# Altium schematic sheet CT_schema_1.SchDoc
size 591 x 258 mm
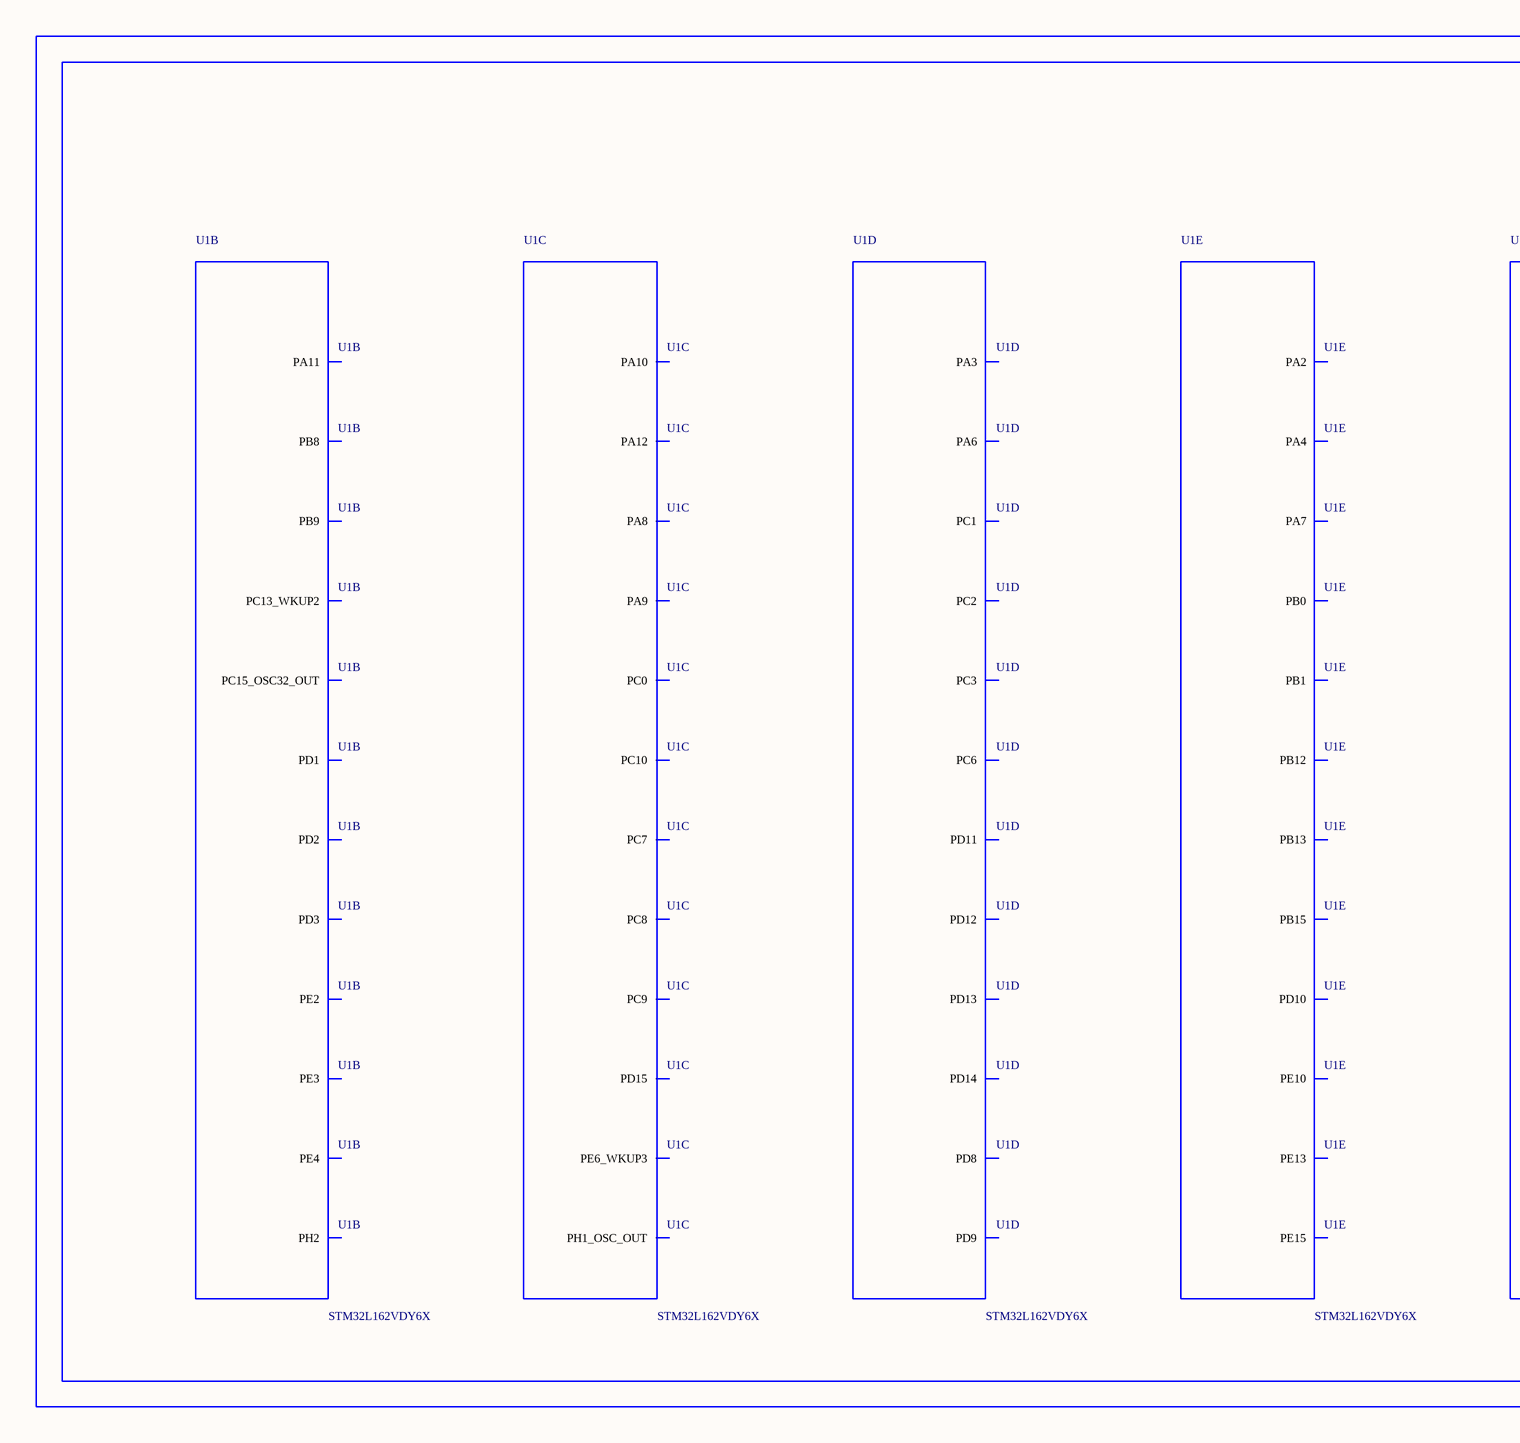
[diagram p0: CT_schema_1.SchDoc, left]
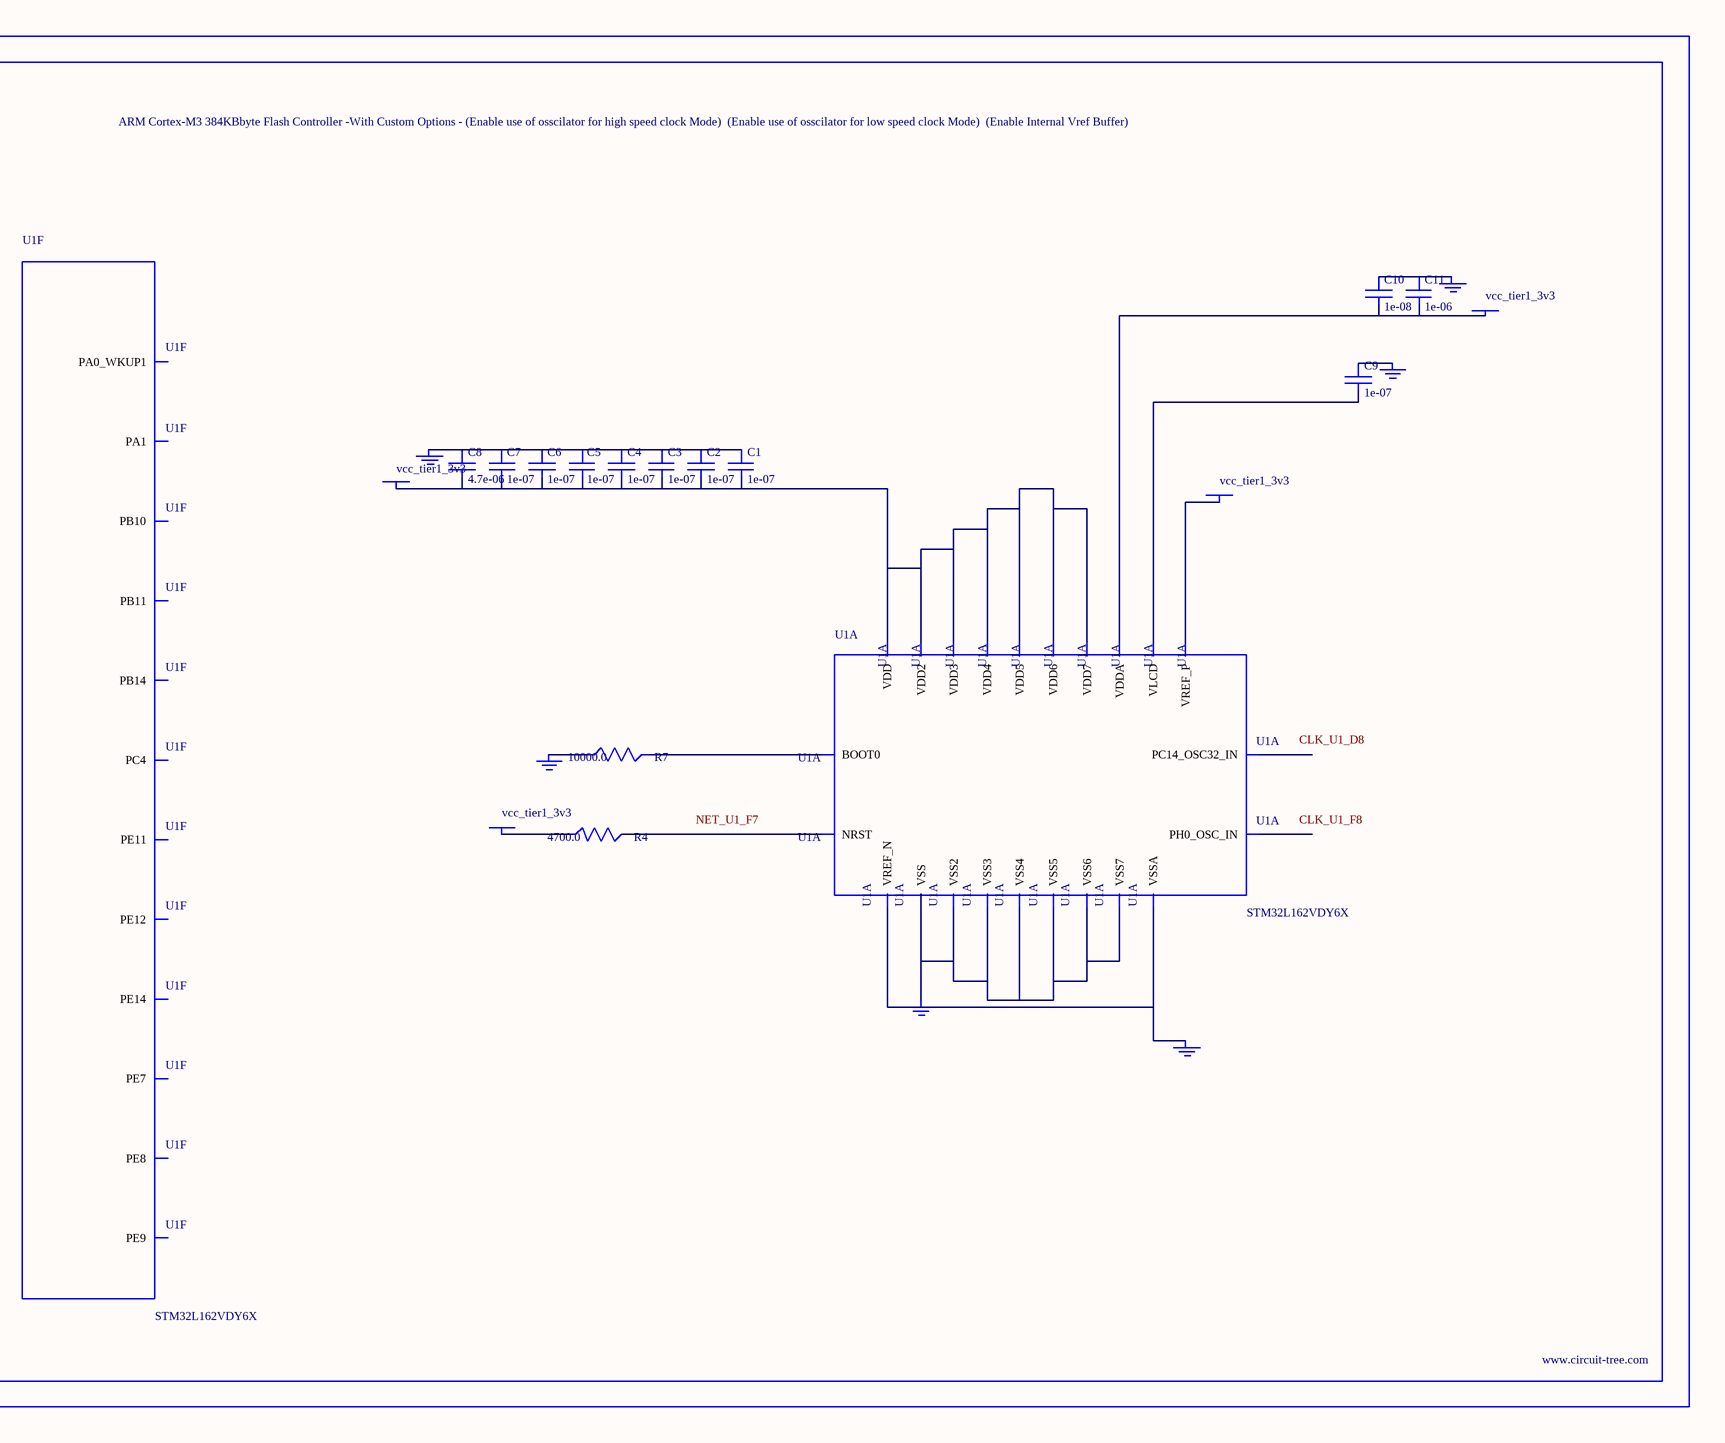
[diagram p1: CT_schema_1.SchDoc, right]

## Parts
BORDER0  (no value)
C1  1e-07  [C0603]
C2  1e-07  [C0603]
C3  1e-07  [C0603]
C4  1e-07  [C0603]
C5  1e-07  [C0603]
C6  1e-07  [C0603]
C7  1e-07  [C0603]
C8  4.7e-06  [C0603]
C9  1e-07  [C0603]
C10  1e-08  [C0603]
C11  1e-06  [C0603]
GND_INSTANCE_0_0  (no value)
GND_INSTANCE_0_1  (no value)
GND_INSTANCE_0_2  (no value)
GND_INSTANCE_0_3  (no value)
GND_INSTANCE_0_4  (no value)
GND_INSTANCE_0_5  (no value)
POWER_INSTANCE_0_0  vcc_tier1_3v3
POWER_INSTANCE_0_1  vcc_tier1_3v3
POWER_INSTANCE_0_2  vcc_tier1_3v3
POWER_INSTANCE_0_3  vcc_tier1_3v3
R4  4700.0  [R0603]
R7  10000.0  [R0603]
U1  STM32L162VDY6X  [WLCSP104]  (parts A,B,C,D,E,F of 9)

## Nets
NetC1_1: C1.1 C2.1 C3.1 C4.1 C5.1 C6.1 C7.1 C8.1 GND_INSTANCE_0_0.0(GND)
NetC1_2: C1.2 C2.2 C3.2 C4.2 C5.2 C6.2 C7.2 C8.2 POWER_INSTANCE_0_0.0(PWR) U1.A9(VDD) U1.B8(VDD2) U1.C1(VDD3) U1.E9(VDD4) U1.K3(VDD5) U1.L8(VDD6) U1.M9(VDD7)
NetC9_1: C9.1 GND_INSTANCE_0_1.0(GND)
NetC9_2: C9.2 U1.E7(VLCD)
NetC10_1: C10.1 C11.1 GND_INSTANCE_0_3.0(GND)
NetC10_2: C10.2 C11.2 POWER_INSTANCE_0_1.0(PWR) U1.G6(VDDA)
NetGND_INSTANCE_0_2_0: GND_INSTANCE_0_2.0(GND) R7.1
NetGND_INSTANCE_0_4_0: GND_INSTANCE_0_4.0(GND) U1.H8(VREF_N) U1.J9(VSSA)
NetGND_INSTANCE_0_5_0: GND_INSTANCE_0_5.0(GND) U1.A1(VSS) U1.C7(VSS2) U1.D2(VSS3) U1.E8(VSS4) U1.K8(VSS5) U1.L2(VSS6) U1.M1(VSS7)
NetPOWER_INSTANCE_0_2_0: POWER_INSTANCE_0_2.0(PWR) U1.G7(VREF_P)
NetPOWER_INSTANCE_0_3_0: POWER_INSTANCE_0_3.0(PWR) R4.1
NetR4_2: R4.2 U1.F7(NRST)
NetR7_2: R7.2 U1.A7(BOOT0)

Not connected (* = marked no-connect by the designer): U1 C3(PD2) C4(PD3) C6(PB9) C8(PE4) C9(PC13_WKUP2) D1(PH2) D4(PD1) D5(PB8) D6(PE2) D7(PE3) D8(PC14_OSC32_IN) D9(PC15_OSC32_OUT) E1(PA11) E2(PA12) E4(PC10) E6(PE6_WKUP3) F1(PA9) F2(PA10) F3(PA8) F4(PC9) F6(PC0) F8(PH0_OSC_IN) F9(PH1_OSC_OUT) G1(PC7) G2(PC8) G3(PD15) G4(PD11) G8(PC3) G9(PC2) H1(PC6) H2(PD13) H3(PD12) H4(PD8) H6(PA6) H7(PA3) H9(PC1) J1(PD14) J2(PD9) J3(PB13) J4(PB12) J5(PE10) J6(PB0) J7(PA4) J8(PA2) K1(PD10) K2(PB15) K4(PE15) K5(PE13) K6(PB1) K7(PA7) K9(PA0_WKUP1) L1(PB14) L3(PB11) L4(PE14) L5(PE11) L6(PE7) L7(PC4) L9(PA1) M2(PB10) M3(PE12) M4(PE9) M5(PE8)

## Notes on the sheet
- Labels drawn without touching a wire or pin: CLK_U1_D8, CLK_U1_F8, NET_U1_F7

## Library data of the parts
BORDER0 = BORDER_PAGE0
C1-C7 C9 = 06035C104K4Z2A
C8 = GRM188R6YA475KE15D
C10 = 06035C103K4Z2A
C11 = C0603C105K3RACTU
GND_INSTANCE_0_0-GND_INSTANCE_0_5 = GND
POWER_INSTANCE_0_0-POWER_INSTANCE_0_3 = PWR
R4 = RC0603JR-074K7L
R7 = RC0603JR-0710KL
